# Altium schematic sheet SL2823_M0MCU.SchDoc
size B; SheetNumber: 0; SheetTotal: 0; PageSetup: Record=PageOptions¦CenterHorizontal=True¦CenterVertical=True¦PrintScale=0.75¦XCorrection=1.00¦YCorrection=1.00¦PrintKind=1¦BorderSize=5000000¦LeftOffset=0¦BottomOffset=0¦Orientation=2¦PaperLength=2970¦PaperWidth=2100¦Scale=100¦PaperSource=257¦PrintQuality=600¦MediaType=1¦DitherType=10¦PrintScaleMode=1¦PaperKind=A4 (210 x 297 毫米)¦PaperIndex=9
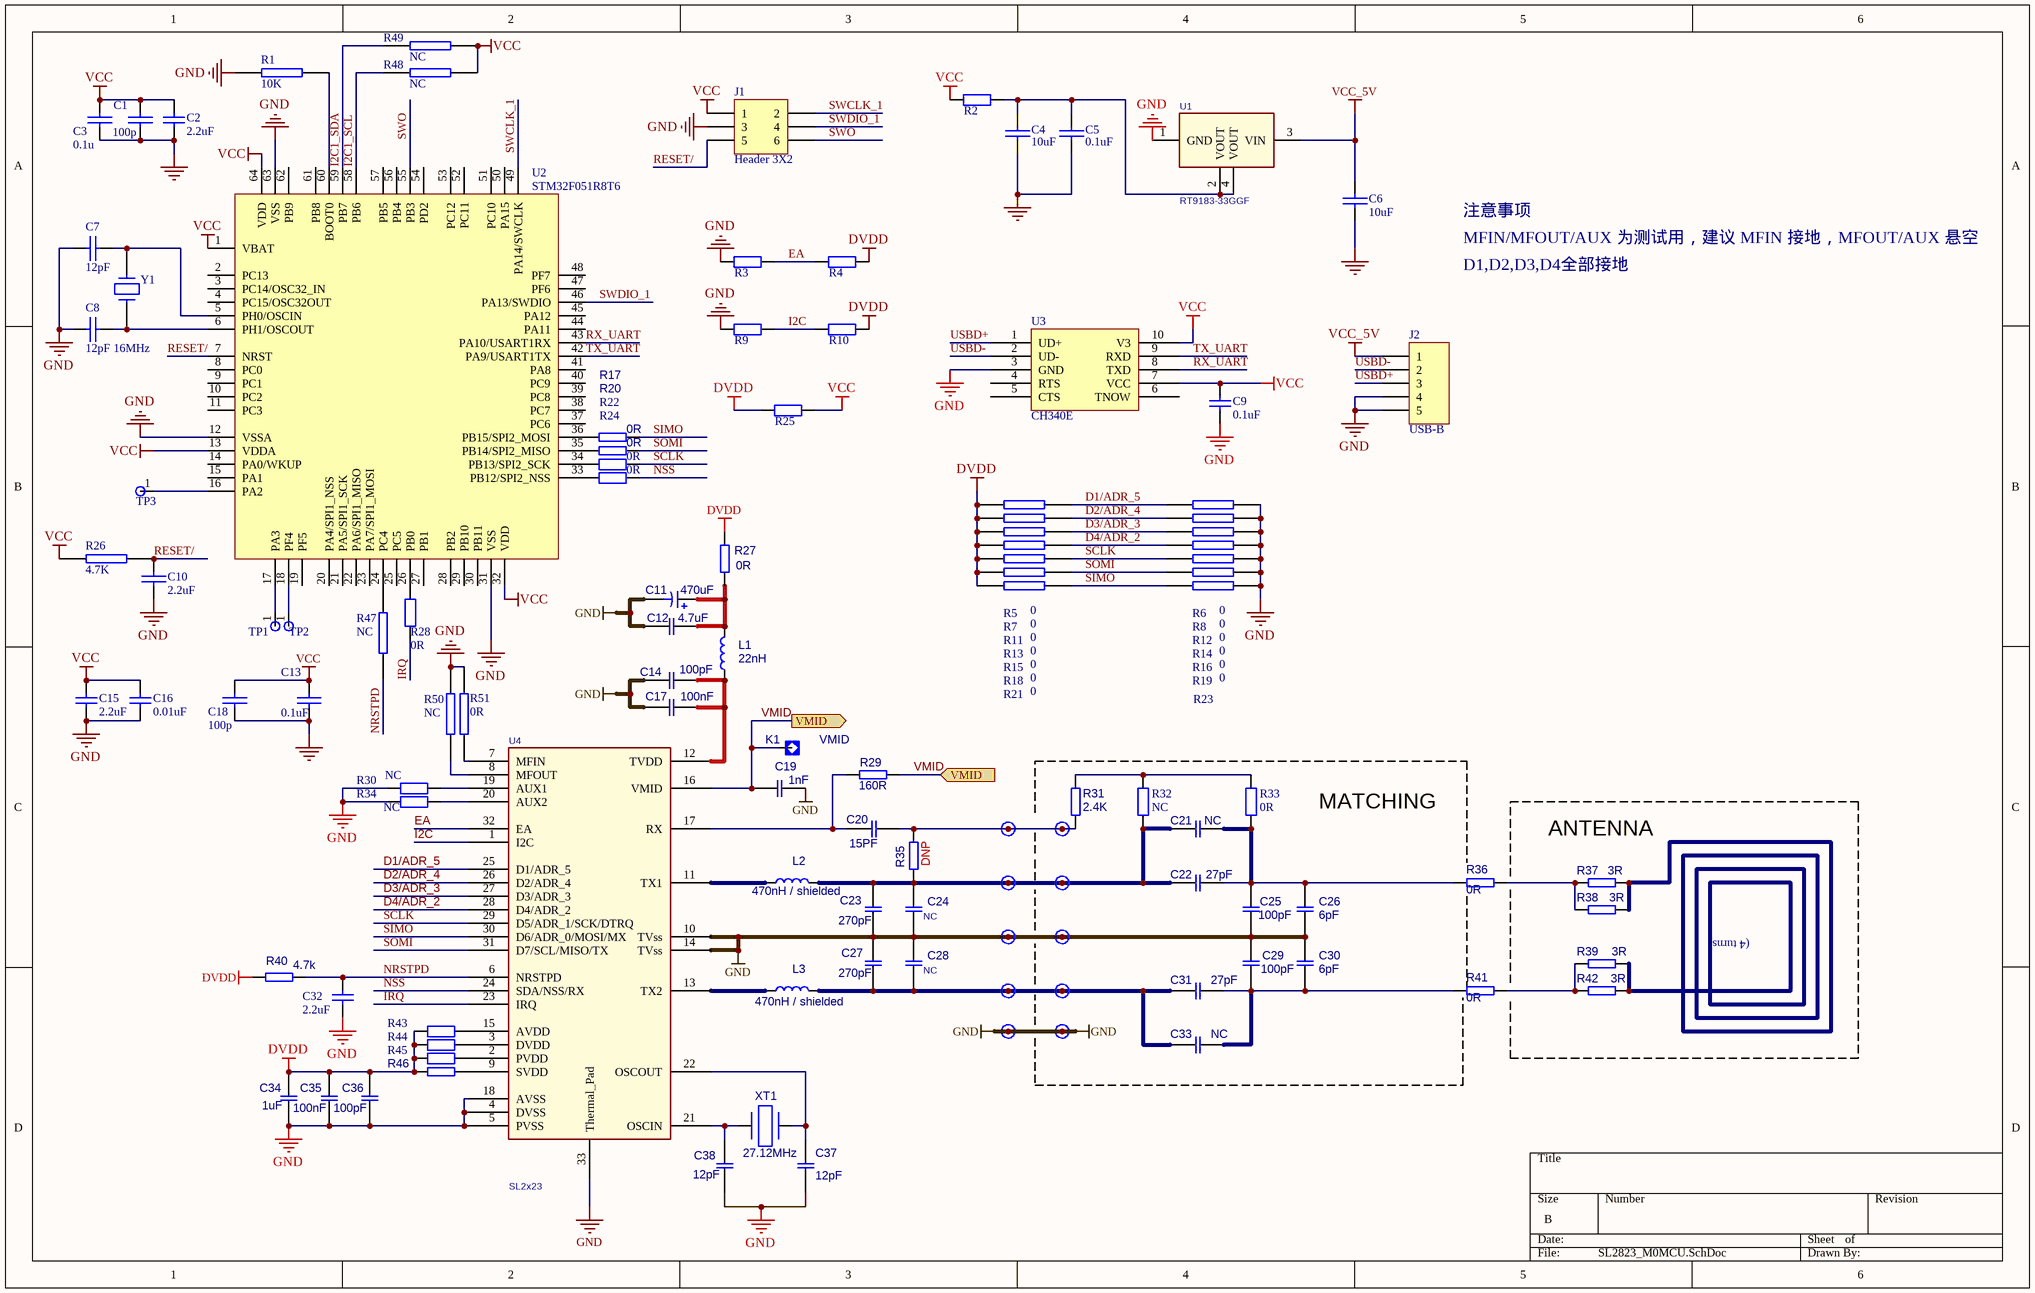
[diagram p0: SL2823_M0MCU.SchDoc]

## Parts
C1  100p  [C_0402]
C2  value 2.2uF  [C_0402]  (hidden comment: Cap)
C3  0.1u  [C_0402]
C4  10uF  [Y0805]
C5  0.1uF  [Y0603]
C6  10uF  [Y0805]
C7  12pF  [C_0402]
C8  12pF  [C_0402]
C9  value 0.1uF  [C_0402]  (hidden comment: Cap)
C10  2.2uF  [C_0402]
C11  value 470uF  [C_TANTAL_D]  (hidden comment: 330uF)
C12  value 4.7uF  [Y0603]  (hidden comment: 100nF)
C13  0.1uF  [C_0402]
C14  100pF  [Y0805]
C15  value 2.2uF  [C_0402]  (hidden comment: Cap)
C16  value 0.01uF  [C_0402]  (hidden comment: Cap)
C17  100nF  [Y0603]
C18  100p  [C_0402]
C19  1nF  [Y0805]
C20  value 15PF  [Y0805]  (hidden comment: 1nF)
C21  value NC  [Y0805]  (hidden comment: 12pF)
C22  27pF  [Y0805]
C23  270pF  [Y0805]
C24  NC  [Y0805]
C25  100pF  [Y0805]
C26  6pF  [Y0805]
C27  270pF  [Y0805]
C28  NC  [Y0805]
C29  100pF  [Y0805]
C30  6pF  [Y0805]
C31  27pF  [Y0805]
C32  value 2.2uF  [Y0805]  (hidden comment: Cap)
C33  value NC  [Y0805]  (hidden comment: 12pF)
C34  value 1uF  [Y0603]  (hidden comment: 100nF)
C35  100nF  [Y0603]
C36  100pF  [Y0603]
C37  12pF  [Y0603]
C38  12pF  [Y0603]
J1  Header 3X2  [JETAG-2]
J2  USB-B  [microusb]
K1  value VMID  [TEST_Point]  (hidden comment: TP1)
K2  TP_0.9mm  [TP_0.9mm]  (value not drawn)
K3  TP_0.9mm  [TP_0.9mm]  (value not drawn)
K4  TP_0.9mm  [TP_0.9mm]  (value not drawn)
K5  TP_0.9mm  [TP_0.9mm]  (value not drawn)
K6  TP_0.9mm  [TP_0.9mm]  (value not drawn)
K7  TP_0.9mm  [TP_0.9mm]  (value not drawn)
K8  TP_0.9mm  [TP_0.9mm]  (value not drawn)
K9  TP_0.9mm  [TP_0.9mm]  (value not drawn)
K10  TP_0.9mm  [TP_0.9mm]  (value not drawn)
K11  TP_0.9mm  [TP_0.9mm]  (value not drawn)
L1  22nH  [Y0805]
L2  value 470nH / shielded  [INDCC_1812]  (hidden comment: 470nH / shielded (1210))
L3  value 470nH / shielded  [INDCC_1812]  (hidden comment: 470nH / shielded (1210))
R1  10K  [R_0402]
R2  16.9  [Y0805]  (value not drawn)
R3  16.9  [R_0402]  (value not drawn)
R4  16.9  [R_0402]  (value not drawn)
R5  0  [R_0402]
R6  0  [R_0402]
R7  0  [R_0402]
R8  0  [R_0402]
R9  16.9  [R_0402]  (value not drawn)
R10  16.9  [R_0402]  (value not drawn)
R11  0  [R_0402]
R12  0  [R_0402]
R13  0  [R_0402]
R14  0  [R_0402]
R15  0  [R_0402]
R16  0  [R_0402]
R17  0R  [Y0805]
R18  0  [R_0402]
R19  0  [R_0402]
R20  value 0R  [Y0805]  (hidden comment: 0R DNP)
R21  0  [R_0402]
R22  0R  [Y0805]
R23  (no value)  [R_0402]
R24  0R  [Y0805]
R25  16.9  [Y0805]  (value not drawn)
R26  4.7K  [R_0402]
R27  0R  [Y0805]
R28  0R  [Y0805]
R29  160R  [Y0805]
R30  NC  [Y0805]
R31  value 2.4K  [Y0805]  (hidden comment: 2k4)
R32  16.9  [Y0603]  (value not drawn)
R33  16.9  [Y0603]  (value not drawn)
R34  NC  [Y0805]
R35  DNP  [Y0805]
R36  0R  [Y0805]
R37  3R  [Y0805]
R38  3R  [Y0805]
R39  3R  [Y0805]
R40  value 4.7k  [Y0805]  (hidden comment: 10k)
R41  value 0R  [Y0805]  (hidden comment: 0R DNP)
R42  3R  [Y0805]
R43  16.9  [Y0603]  (value not drawn)
R44  16.9  [Y0805]  (value not drawn)
R45  16.9  [Y0805]  (value not drawn)
R46  0R DNP  [Y0805]  (value not drawn)
R47  NC  [R_0402]
R48  NC  [R_0402]
R49  NC  [R_0402]
R50  NC  [R_0402]
R51  0R  [R_0402]
TP1  Test_Point  [TEST_Point]  (value not drawn)
TP2  Test_Point  [TEST_Point]  (value not drawn)
TP3  Test_Point  [TEST_Point]  (value not drawn)
U1  RT9183-33GGF  [RT9183-33GG]
U2  STM32F051R8T6  [QFN64-STM32]
U3  CH340E  [CH340E_MSOP10]
U4  SL2x23  [Z_QFN50P500X500X100-32N]
XT1  27.12MHz  [QUARTZ_32SMX]
Y1  16MHz  [Z-OSC]

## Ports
VMID (in), VMID (out)

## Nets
DVDD: C34.2 C35.2 C36.2 R4.1 R5.1 R7.1 R10.2 R11.1 R13.1 R15.1 R18.1 R21.1 R25.1 R27.2 R40.1 R43.1 R44.1 R45.1 R46.1
GND: C1.2 C2.2 C3.2 C4.2 C5.2 C6.2 C7.1 C8.2 C9.2 C10.2 C11.2 C12.1 C13.2 C14.1 C15.1 C16.2 C17.1 C18.2 C19.2 C23.1 C24.1 C25.1 C26.1 C27.2 C28.2 C29.2 C30.2 C32.1 C34.1 C35.1 C36.1 C37.1 C38.1 J1.3 J2.4 J2.5 K6.1 K7.1 K10.1 K11.1 R1.2 R3.1 R6.2 R8.2 R9.1 R12.2 R14.2 R16.2 R19.2 R23.2 R30.1 R34.1 R50.1 R51.1 U1.1(GND) U2.12(VSSA) U2.31(VSS) U2.63(VSS) U3.3(GND) U4.4(DVSS) U4.5(PVSS) U4.10(TVss) U4.14(TVss) U4.18(AVSS) U4.33(Thermal_Pad)
VCC: C1.1 C2.1 C3.1 C9.1 C13.1 C15.2 C16.1 C18.1 J1.1 R2.1 R25.2 R26.2 R48.1 R49.1 U2.1(VBAT) U2.13(VDDA) U2.32(VDD) U2.64(VDD) U3.7(VCC) U3.10(V3)
VCC_5V: C6.1 J2.1 U1.3(VIN)
D1/ADR_5: R5.2 R6.1 U4.25(D1/ADR_5)
D2/ADR_4: R7.2 R8.1 U4.26(D2/ADR_4)
D3/ADR_3: R11.2 R12.1 U4.27(D3/ADR_3)
D4/ADR_2: R13.2 R14.1 U4.28(D4/ADR_2)
EA: R3.2 R4.2 U4.32(EA)
I2C: R9.2 R10.1 U4.1(I2C)
I2C1_SCL: R48.2 U2.58(PB6)
I2C1_SDA: R49.2 U2.59(PB7)
IRQ: R28.1 U4.23(IRQ)
NRSTPD: C32.2 R40.2 R47.2 U4.6(NRSTPD)
NSS: R24.2 U4.24(SDA/NSS/RX)
RESET/: C10.1 J1.5 R26.1 U2.7(NRST)
RX_UART: U2.43(PA10/USART1RX) U3.8(TXD)
SCLK: R15.2 R16.1 R22.2 U4.29(D5/ADR_1/SCK/DTRQ)
SIMO: R17.1 R21.2 R23.1 U4.30(D6/ADR_0/MOSI/MX)
SOMI: R18.2 R19.1 R20.1 U4.31(D7/SCL/MISO/TX)
SWCLK_1: J1.2 U2.49(PA14/SWCLK)
SWDIO_1: J1.4 U2.46(PA13/SWDIO)
SWO: J1.6 U2.55(PB3)
TX_UART: U2.42(PA9/USART1TX) U3.9(RXD)
USBD+: J2.3 U3.1(UD+)
USBD-: J2.2 U3.2(UD-)
VMID: C19.1 K1.1 R29.2 U4.16(VMID) ; port VMID
NetC4_1: C4.1 C5.1 R2.2 U1.2(VOUT) U1.4(VOUT)
NetC7_2: C7.2 U2.5(PH0/OSCIN) Y1.2
NetC8_1: C8.1 U2.6(PH1/OSCOUT) Y1.1
NetC11_1: C11.1 C12.2 L1.2 R27.1
NetC14_2: C14.2 C17.2 L1.1 U4.12(TVDD)
NetC20_1: C20.1 R29.1 U4.17(RX)
NetC20_2: C20.2 K2.1 K3.1 R31.2 R35.1
NetC21_1: C21.1 C22.1 C23.2 C24.2 K4.1 K5.1 L2.2 R32.1 R35.2
NetC21_2: C21.2 C22.2 C25.2 C26.2 R33.1 R36.2
NetC27_1: C27.1 C28.1 C31.1 C33.1 K8.1 K9.1 L3.2
NetC29_1: C29.1 C30.1 C31.2 C33.2 R41.2
NetC37_2: C37.2 U4.22(OSCOUT) XT1.3
NetC38_2: C38.2 U4.21(OSCIN) XT1.1
NetL2_1: L2.1 U4.11(TX1)
NetL3_1: L3.1 U4.13(TX2)
NetR1_1: R1.1 U2.60(BOOT0)
NetR17_2: R17.2 U2.36(PB15/SPI2_MOSI)
NetR20_2: R20.2 U2.35(PB14/SPI2_MISO)
NetR22_1: R22.1 U2.34(PB13/SPI2_SCK)
NetR24_1: R24.1 U2.33(PB12/SPI2_NSS)
NetR28_2: R28.2 U2.26(PB0)
NetR30_2: R30.2 U4.19(AUX1)
NetR31_1: R31.1 R32.2 R33.2
NetR34_2: R34.2 U4.20(AUX2)
NetR36_1: R36.1 R37.2 R38.2
NetR37_1: R37.1 R38.1 R39.1 R42.1
NetR39_2: R39.2 R41.1 R42.2
NetR43_2: R43.2 U4.15(AVDD)
NetR44_2: R44.2 U4.3(DVDD)
NetR45_2: R45.2 U4.2(PVDD)
NetR46_2: R46.2 U4.9(SVDD)
NetR47_1: R47.1 U2.24(PC4)
NetR50_2: R50.2 U4.8(MFOUT)
NetR51_2: R51.2 U4.7(MFIN)
NetTP1_1: TP1.1(TP) U2.17(PA3)
NetTP2_1: TP2.1(TP) U2.18(PF4)
NetTP3_1: TP3.1(TP) U2.16(PA2)

Not connected (* = marked no-connect by the designer): U2 2(PC13) 3(PC14/OSC32_IN) 4(PC15/OSC32OUT) 8(PC0) 9(PC1) 10(PC2) 11(PC3) 14(PA0/WKUP) 15(PA1) 19(PF5) 20(PA4/SPI1_NSS) 21(PA5/SPI1_SCK) 22(PA6/SPI1_MISO) 23(PA7/SPI1_MOSI) 25(PC5) 27(PB1) 28(PB2) 29(PB10) 30(PB11) 37(PC6) 38(PC7) 39(PC8) 40(PC9) 41(PA8) 44(PA11) 45(PA12) 47(PF6) 48(PF7) 50(PA15) 51(PC10) 52(PC11) 53(PC12) 54(PD2) 56(PB4) 57(PB5) 61(PB8) 62(PB9); U3 4(RTS) 5(CTS) 6(TNOW); XT1 2 4

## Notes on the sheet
- 注意事项
- MFIN/MFOUT/AUX 为测试用，建议 MFIN 接地，MFOUT/AUX 悬空
- D1,D2,D3,D4全部接地
- MATCHING
- (near R37) ANTENNA
- (4 turns)

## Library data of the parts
C1 C3-C8 C10 C13 C18 = CAP: Capacitor
C2 C9 C15 C16 C32 = Cap: Capacitor
C11 = C_TANTAL_D
C12 C17 C19 C34-C38 = CAPC0603
C14 C20-C23 C25 C27 C29 C31 C33 = CAPC0805
C24 C28 = CAPC0805: Value: 150pF
C26 C30 = CAPC0805: Value: DNP
J1 = Header 3X2: Header, 3-Pin, Dual row
J2 = Header 5: Header, 5-Pin
L1 = INDC0805
L2 L3 = INDC1812
R1 R5-R8 R11-R16 R18 R19 R21 R23 R26 R47-R51 = RES2
R2-R4 R9 R10 R22 R24 R25 R28 R30 R32-R34 R43-R45 = Res2: 0
R17 R20 R27 R29 R31 R35-R42 R46 = RESC0805
U3 = CH340-E
U4 = SL2523
XT1 = QUARTZ_32SMX
Y1 = CRYSTAL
